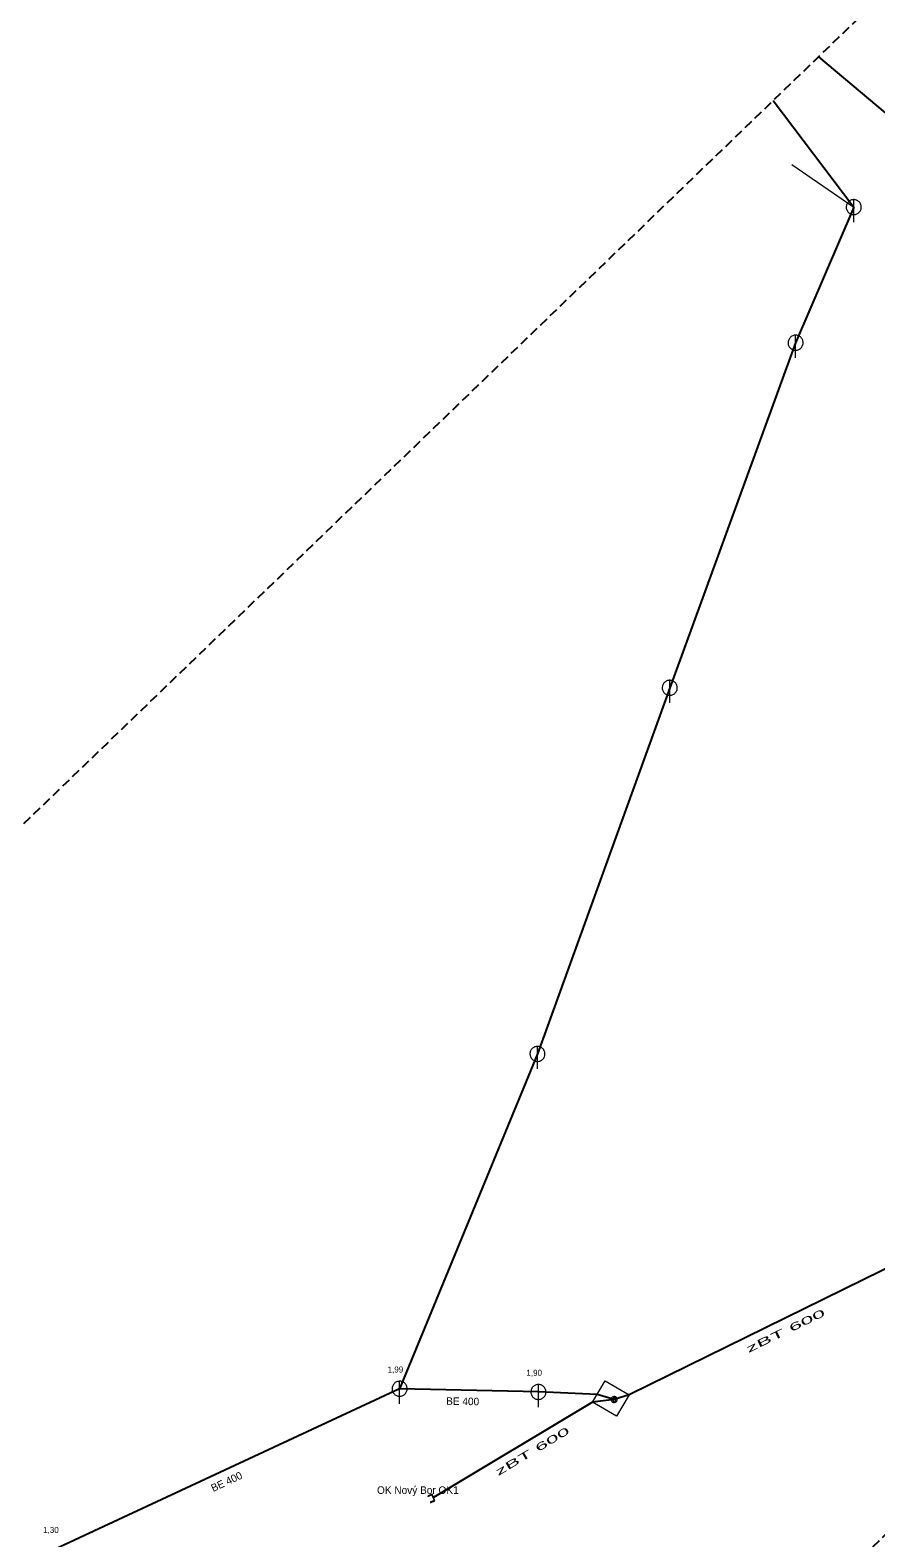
# Model space of a CAD drawing. Extents: x -724334 to -723692, y -972150 to -970648.
# Drawn here: x -724118 to -724005.6, y -971004.7 to -970804.3 of the extents above; entities that cross this region are included whole.
import ezdxf

# ---------------------------------------------------------------- set-up
doc = ezdxf.new("R2010")
doc.units = 0
doc.header["$LTSCALE"] = 0.4
doc.linetypes.add('MEDIUM_DASHED', pattern=[4.5, 3, -1.5])
for name, color, linetype, lineweight in [('1', 7, 'Continuous', 25), ('11', 7, 'Continuous', 13), ('14', 7, 'Continuous', 25), ('22', 7, 'Continuous', 13), ('29', 7, 'Continuous', 13)]:
    doc.layers.add(name, color=color, linetype=linetype, lineweight=lineweight)

msp = doc.modelspace()

# ---------------------------------------------------------------- linework, layer by layer
at = {"layer": '1', "linetype": 'MEDIUM_DASHED'}
msp.add_lwpolyline([(-723848.074, -970648.428), (-723714.095, -970720.999), (-724065.788, -971064.318), (-723792.249, -971201.088), (-723702.93, -971508.122), (-723691.766, -972150.101), (-723842.491, -972097.068), (-723864.821, -971424.385), (-723982.052, -971259.703), (-724333.745, -971117.352)], close=True, dxfattribs=at)
at = {"layer": '1', "lineweight": 13}
msp.add_lwpolyline([(-724043.239, -970986.71), (-724041.559, -970983.87), (-724038.379, -970985.76), (-724040.059, -970988.59)], close=True, dxfattribs=at)
at = {"layer": '11'}
msp.add_line((-724016.767, -970822.217), (-724008.55, -970827.87), dxfattribs=at)
at = {"layer": '14'}
for p, q in [((-724013.248, -970807.906), (-723998.093, -970820.63)), ((-724019.26, -970813.711), (-724008.55, -970827.87)), ((-724008.55, -970827.87), (-724016.27, -970845.89)), ((-724016.27, -970845.89), (-724032.99, -970891.76)), ((-724032.99, -970891.76), (-724050.565, -970940.422)), ((-724050.565, -970940.421), (-724068.879, -970984.93)), ((-724068.879, -970984.93), (-724114.64, -971006.25)), ((-724050.44, -970985.359), (-724068.879, -970984.93))]:
    msp.add_line(p, q, dxfattribs=at)
for points in [[(-724002.16, -970967.949), (-724038.379, -970985.76), (-724040.368, -970986.355)], [(-724040.368, -970986.355), (-724043.239, -970986.71), (-724064.379, -970999.39)], [(-724040.368, -970986.355), (-724042.629, -970985.68), (-724050.44, -970985.359)]]:
    msp.add_lwpolyline(points, dxfattribs=at)
at = {"layer": '22'}
for p, q in [((-724008.55, -970829.87), (-724008.549, -970826.87)), ((-724016.27, -970847.89), (-724016.269, -970844.89)), ((-724032.989, -970893.76), (-724032.988, -970890.76)), ((-724050.565, -970942.421), (-724050.564, -970939.421)), ((-724068.879, -970986.93), (-724068.878, -970983.93)), ((-724050.44, -970987.359), (-724050.439, -970984.359))]:
    msp.add_line(p, q, dxfattribs=at)
for points in [[(-724007.55, -970827.87), (-724007.555, -970827.761), (-724007.573, -970827.653), (-724007.603, -970827.547), (-724007.643, -970827.446), (-724007.695, -970827.349), (-724007.757, -970827.259), (-724007.829, -970827.176), (-724007.909, -970827.102), (-724007.997, -970827.036), (-724008.091, -970826.981), (-724008.191, -970826.936), (-724008.296, -970826.903), (-724008.403, -970826.881), (-724008.512, -970826.871), (-724008.622, -970826.873), (-724008.73, -970826.887), (-724008.837, -970826.912), (-724008.94, -970826.949), (-724009.038, -970826.998), (-724009.13, -970827.056), (-724009.216, -970827.125), (-724009.293, -970827.202), (-724009.362, -970827.288), (-724009.421, -970827.38), (-724009.469, -970827.478), (-724009.506, -970827.581), (-724009.532, -970827.688), (-724009.546, -970827.796), (-724009.549, -970827.906), (-724009.539, -970828.015), (-724009.518, -970828.122), (-724009.484, -970828.226), (-724009.44, -970828.326), (-724009.385, -970828.421), (-724009.319, -970828.509), (-724009.245, -970828.589), (-724009.162, -970828.661), (-724009.072, -970828.723), (-724008.976, -970828.775), (-724008.874, -970828.816), (-724008.769, -970828.846), (-724008.661, -970828.864), (-724008.551, -970828.87), (-724008.442, -970828.864), (-724008.334, -970828.846), (-724008.229, -970828.817), (-724008.127, -970828.776), (-724008.03, -970828.724), (-724007.94, -970828.662), (-724007.857, -970828.591), (-724007.782, -970828.511), (-724007.717, -970828.423), (-724007.661, -970828.329), (-724007.617, -970828.229), (-724007.583, -970828.125), (-724007.561, -970828.017), (-724007.551, -970827.908)], [(-724015.27, -970845.89), (-724015.275, -970845.781), (-724015.293, -970845.673), (-724015.323, -970845.567), (-724015.363, -970845.466), (-724015.415, -970845.369), (-724015.477, -970845.279), (-724015.549, -970845.196), (-724015.629, -970845.122), (-724015.717, -970845.056), (-724015.811, -970845.001), (-724015.911, -970844.956), (-724016.016, -970844.923), (-724016.123, -970844.901), (-724016.232, -970844.891), (-724016.342, -970844.893), (-724016.45, -970844.907), (-724016.557, -970844.932), (-724016.66, -970844.969), (-724016.758, -970845.018), (-724016.85, -970845.076), (-724016.936, -970845.145), (-724017.013, -970845.222), (-724017.082, -970845.308), (-724017.141, -970845.4), (-724017.189, -970845.498), (-724017.226, -970845.601), (-724017.252, -970845.708), (-724017.266, -970845.816), (-724017.269, -970845.926), (-724017.259, -970846.035), (-724017.238, -970846.142), (-724017.204, -970846.246), (-724017.16, -970846.346), (-724017.105, -970846.441), (-724017.039, -970846.529), (-724016.965, -970846.609), (-724016.882, -970846.681), (-724016.792, -970846.743), (-724016.696, -970846.795), (-724016.594, -970846.836), (-724016.489, -970846.866), (-724016.381, -970846.884), (-724016.271, -970846.89), (-724016.162, -970846.884), (-724016.054, -970846.866), (-724015.949, -970846.837), (-724015.847, -970846.796), (-724015.75, -970846.744), (-724015.66, -970846.682), (-724015.577, -970846.611), (-724015.502, -970846.531), (-724015.437, -970846.443), (-724015.381, -970846.349), (-724015.337, -970846.249), (-724015.303, -970846.145), (-724015.281, -970846.037), (-724015.271, -970845.928)], [(-724031.989, -970891.76), (-724031.994, -970891.651), (-724032.012, -970891.543), (-724032.042, -970891.437), (-724032.082, -970891.336), (-724032.134, -970891.239), (-724032.196, -970891.149), (-724032.268, -970891.066), (-724032.348, -970890.992), (-724032.436, -970890.926), (-724032.53, -970890.871), (-724032.63, -970890.826), (-724032.735, -970890.793), (-724032.842, -970890.771), (-724032.951, -970890.761), (-724033.061, -970890.763), (-724033.169, -970890.777), (-724033.276, -970890.802), (-724033.379, -970890.839), (-724033.477, -970890.888), (-724033.569, -970890.946), (-724033.655, -970891.015), (-724033.732, -970891.092), (-724033.801, -970891.178), (-724033.86, -970891.27), (-724033.908, -970891.368), (-724033.945, -970891.471), (-724033.971, -970891.578), (-724033.985, -970891.686), (-724033.988, -970891.796), (-724033.978, -970891.905), (-724033.957, -970892.012), (-724033.923, -970892.116), (-724033.879, -970892.216), (-724033.824, -970892.311), (-724033.758, -970892.399), (-724033.684, -970892.479), (-724033.601, -970892.551), (-724033.511, -970892.613), (-724033.415, -970892.665), (-724033.313, -970892.706), (-724033.208, -970892.736), (-724033.1, -970892.754), (-724032.99, -970892.76), (-724032.881, -970892.754), (-724032.773, -970892.736), (-724032.668, -970892.707), (-724032.566, -970892.666), (-724032.469, -970892.614), (-724032.379, -970892.552), (-724032.296, -970892.481), (-724032.221, -970892.401), (-724032.156, -970892.313), (-724032.1, -970892.219), (-724032.056, -970892.119), (-724032.022, -970892.015), (-724032, -970891.907), (-724031.99, -970891.798)], [(-724049.565, -970940.421), (-724049.57, -970940.312), (-724049.588, -970940.204), (-724049.618, -970940.098), (-724049.658, -970939.997), (-724049.71, -970939.9), (-724049.772, -970939.81), (-724049.844, -970939.727), (-724049.924, -970939.653), (-724050.012, -970939.587), (-724050.106, -970939.532), (-724050.206, -970939.487), (-724050.311, -970939.454), (-724050.418, -970939.432), (-724050.527, -970939.422), (-724050.637, -970939.424), (-724050.745, -970939.438), (-724050.852, -970939.463), (-724050.955, -970939.5), (-724051.053, -970939.549), (-724051.145, -970939.607), (-724051.231, -970939.676), (-724051.308, -970939.753), (-724051.377, -970939.839), (-724051.436, -970939.931), (-724051.484, -970940.029), (-724051.521, -970940.132), (-724051.547, -970940.239), (-724051.561, -970940.347), (-724051.564, -970940.457), (-724051.554, -970940.566), (-724051.533, -970940.673), (-724051.499, -970940.777), (-724051.455, -970940.877), (-724051.4, -970940.972), (-724051.334, -970941.06), (-724051.26, -970941.14), (-724051.177, -970941.212), (-724051.087, -970941.274), (-724050.991, -970941.326), (-724050.889, -970941.367), (-724050.784, -970941.397), (-724050.676, -970941.415), (-724050.566, -970941.421), (-724050.457, -970941.415), (-724050.349, -970941.397), (-724050.244, -970941.368), (-724050.142, -970941.327), (-724050.045, -970941.275), (-724049.955, -970941.213), (-724049.872, -970941.142), (-724049.797, -970941.062), (-724049.732, -970940.974), (-724049.676, -970940.88), (-724049.632, -970940.78), (-724049.598, -970940.676), (-724049.576, -970940.568), (-724049.566, -970940.459)], [(-724067.879, -970984.93), (-724067.884, -970984.821), (-724067.902, -970984.713), (-724067.932, -970984.607), (-724067.972, -970984.506), (-724068.024, -970984.409), (-724068.086, -970984.319), (-724068.158, -970984.236), (-724068.238, -970984.162), (-724068.326, -970984.096), (-724068.42, -970984.041), (-724068.52, -970983.996), (-724068.625, -970983.963), (-724068.732, -970983.941), (-724068.841, -970983.931), (-724068.951, -970983.933), (-724069.059, -970983.947), (-724069.166, -970983.972), (-724069.269, -970984.009), (-724069.367, -970984.058), (-724069.459, -970984.116), (-724069.545, -970984.185), (-724069.622, -970984.262), (-724069.691, -970984.348), (-724069.75, -970984.44), (-724069.798, -970984.538), (-724069.835, -970984.641), (-724069.861, -970984.748), (-724069.875, -970984.856), (-724069.878, -970984.966), (-724069.868, -970985.075), (-724069.847, -970985.182), (-724069.813, -970985.286), (-724069.769, -970985.386), (-724069.714, -970985.481), (-724069.648, -970985.569), (-724069.574, -970985.649), (-724069.491, -970985.721), (-724069.401, -970985.783), (-724069.305, -970985.835), (-724069.203, -970985.876), (-724069.098, -970985.906), (-724068.99, -970985.924), (-724068.88, -970985.93), (-724068.771, -970985.924), (-724068.663, -970985.906), (-724068.558, -970985.877), (-724068.456, -970985.836), (-724068.359, -970985.784), (-724068.269, -970985.722), (-724068.186, -970985.651), (-724068.111, -970985.571), (-724068.046, -970985.483), (-724067.99, -970985.389), (-724067.946, -970985.289), (-724067.912, -970985.185), (-724067.89, -970985.077), (-724067.88, -970984.968)], [(-724049.44, -970985.359), (-724049.445, -970985.25), (-724049.463, -970985.142), (-724049.493, -970985.036), (-724049.533, -970984.935), (-724049.585, -970984.838), (-724049.647, -970984.748), (-724049.719, -970984.665), (-724049.799, -970984.591), (-724049.887, -970984.525), (-724049.981, -970984.47), (-724050.081, -970984.425), (-724050.186, -970984.392), (-724050.293, -970984.37), (-724050.402, -970984.36), (-724050.512, -970984.362), (-724050.62, -970984.376), (-724050.727, -970984.401), (-724050.83, -970984.438), (-724050.928, -970984.487), (-724051.02, -970984.545), (-724051.106, -970984.614), (-724051.183, -970984.691), (-724051.252, -970984.777), (-724051.311, -970984.869), (-724051.359, -970984.967), (-724051.396, -970985.07), (-724051.422, -970985.177), (-724051.436, -970985.285), (-724051.439, -970985.395), (-724051.429, -970985.504), (-724051.408, -970985.611), (-724051.374, -970985.715), (-724051.33, -970985.815), (-724051.275, -970985.91), (-724051.209, -970985.998), (-724051.135, -970986.078), (-724051.052, -970986.15), (-724050.962, -970986.212), (-724050.866, -970986.264), (-724050.764, -970986.305), (-724050.659, -970986.335), (-724050.551, -970986.353), (-724050.441, -970986.359), (-724050.332, -970986.353), (-724050.224, -970986.335), (-724050.119, -970986.306), (-724050.017, -970986.265), (-724049.92, -970986.213), (-724049.83, -970986.151), (-724049.747, -970986.08), (-724049.672, -970986), (-724049.607, -970985.912), (-724049.551, -970985.818), (-724049.507, -970985.718), (-724049.473, -970985.614), (-724049.451, -970985.506), (-724049.441, -970985.397)], [(-724039.977, -970986.358), (-724039.983, -970986.29), (-724040.001, -970986.223), (-724040.03, -970986.161), (-724040.07, -970986.104), (-724040.118, -970986.056), (-724040.175, -970986.016), (-724040.237, -970985.987), (-724040.303, -970985.969), (-724040.372, -970985.962), (-724040.441, -970985.968), (-724040.507, -970985.986), (-724040.57, -970986.014), (-724040.626, -970986.054), (-724040.675, -970986.102), (-724040.715, -970986.158), (-724040.745, -970986.22), (-724040.763, -970986.287), (-724040.77, -970986.355), (-724040.764, -970986.424), (-724040.747, -970986.491), (-724040.718, -970986.553), (-724040.679, -970986.61), (-724040.631, -970986.659), (-724040.575, -970986.699), (-724040.513, -970986.729), (-724040.447, -970986.748), (-724040.378, -970986.755), (-724040.309, -970986.749), (-724040.243, -970986.732), (-724040.18, -970986.704), (-724040.123, -970986.665), (-724040.074, -970986.617), (-724040.033, -970986.561), (-724040.003, -970986.499), (-724039.985, -970986.433), (-724039.977, -970986.365)], [(-724040.363, -970986.66), (-724040.326, -970986.653), (-724040.291, -970986.635), (-724040.259, -970986.606), (-724040.231, -970986.567), (-724040.209, -970986.52), (-724040.193, -970986.467), (-724040.184, -970986.41), (-724040.183, -970986.35), (-724040.189, -970986.291), (-724040.202, -970986.236), (-724040.221, -970986.185), (-724040.247, -970986.142), (-724040.277, -970986.108), (-724040.311, -970986.084), (-724040.347, -970986.072), (-724040.384, -970986.071), (-724040.42, -970986.083), (-724040.454, -970986.105), (-724040.485, -970986.139), (-724040.51, -970986.181), (-724040.53, -970986.232), (-724040.543, -970986.287), (-724040.548, -970986.346), (-724040.547, -970986.405), (-724040.538, -970986.463), (-724040.522, -970986.516), (-724040.499, -970986.564), (-724040.472, -970986.604), (-724040.44, -970986.633), (-724040.405, -970986.652), (-724040.368, -970986.66)]]:
    msp.add_lwpolyline(points, close=True, dxfattribs=at)
at = {"layer": '29'}
for points in [[(-724064.761, -971000.087), (-724064.188, -970999.848), (-724064.57, -970998.932), (-724065.144, -970999.172)], [(-724065.11, -970999.252), (-724064.617, -970999.045), (-724064.302, -970999.8), (-724064.796, -971000.006)]]:
    msp.add_lwpolyline(points, dxfattribs=at)

# ---------------------------------------------------------------- texts
at = {"layer": '1'}
for rotation, width, p in [(26, 2.3, (-724022.534, -970980.18)), (31, 2.25, (-724055.79, -970996.552))]:
    msp.add_text('zBT 600 ', height=1, rotation=rotation, dxfattribs=dict(at, width=width)).set_placement(p)
for s, height, p in [('1,99', 0.8, (-724070.479, -970982.777)), ('1,90', 0.8, (-724052.039, -970983.207)), ('OK Nový Bor OK1 ', 1, (-724071.88, -970998.904)), ('1,30', 0.8, (-724116.24, -971004.097))]:
    msp.add_text(s, height=height, dxfattribs=at).set_placement(p)
for rotation, p in [(359, (-724062.704, -970987.058)), (25, (-724093.64, -970998.656))]:
    msp.add_text('BE 400', height=1, rotation=rotation, dxfattribs=at).set_placement(p)

doc.saveas('drawing.dxf')
